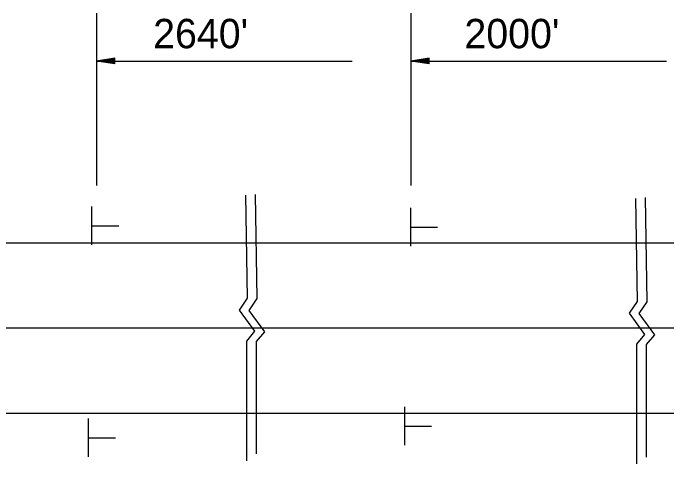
# Model space of a CAD drawing. Extents: x 1374027 to 1374537, y 380415 to 381405.
# Drawn here: x 1374072.71 to 1374086.06, y 380929.4 to 380938.61 of the extents above; entities that cross this region are included whole.
import ezdxf

# ---------------------------------------------------------------- set-up
doc = ezdxf.new("R2010")
doc.units = 0
doc.layers.add('Default', color=7, linetype='Continuous')

msp = doc.modelspace()

# ---------------------------------------------------------------- linework, layer by layer
at = {"layer": 'Default'}
for p, q in [((1374074.415, 380938.607), (1374074.415, 380935.086)), ((1374080.831, 380938.607), (1374080.831, 380935.086)), ((1374074.79, 380937.684), (1374074.415, 380937.627)), ((1374074.79, 380937.674), (1374074.478, 380937.627)), ((1374074.79, 380937.665), (1374074.542, 380937.627)), ((1374074.79, 380937.571), (1374074.79, 380937.684)), ((1374081.206, 380937.684), (1374080.831, 380937.627)), ((1374081.206, 380937.674), (1374080.894, 380937.627)), ((1374081.206, 380937.665), (1374080.958, 380937.627)), ((1374081.206, 380937.571), (1374081.206, 380937.684)), ((1374074.415, 380937.627), (1374079.634, 380937.627)), ((1374074.79, 380937.571), (1374074.415, 380937.627)), ((1374074.79, 380937.581), (1374074.478, 380937.627)), ((1374074.79, 380937.59), (1374074.542, 380937.627)), ((1374074.79, 380937.655), (1374074.605, 380937.627)), ((1374074.79, 380937.6), (1374074.605, 380937.627)), ((1374074.79, 380937.646), (1374074.668, 380937.627)), ((1374074.79, 380937.609), (1374074.668, 380937.627)), ((1374074.79, 380937.636), (1374074.731, 380937.627)), ((1374074.79, 380937.619), (1374074.731, 380937.627)), ((1374080.831, 380937.627), (1374086.05, 380937.627)), ((1374081.206, 380937.571), (1374080.831, 380937.627)), ((1374081.206, 380937.581), (1374080.894, 380937.627)), ((1374081.206, 380937.59), (1374080.958, 380937.627)), ((1374081.206, 380937.655), (1374081.021, 380937.627)), ((1374081.206, 380937.6), (1374081.021, 380937.627)), ((1374081.206, 380937.646), (1374081.084, 380937.627)), ((1374081.206, 380937.609), (1374081.084, 380937.627)), ((1374081.206, 380937.636), (1374081.147, 380937.627)), ((1374081.206, 380937.619), (1374081.147, 380937.627)), ((1374074.324, 380933.872), (1374074.324, 380934.654)), ((1374080.831, 380933.848), (1374080.831, 380934.631)), ((1374074.336, 380934.261), (1374074.87, 380934.261)), ((1374080.843, 380934.238), (1374081.377, 380934.238)), ((1374039.716, 380933.916), (1374181.443, 380933.916)), ((1374039.716, 380932.177), (1374181.443, 380932.177)), ((1374080.705, 380929.784), (1374080.705, 380930.566)), ((1374039.716, 380930.439), (1374181.443, 380930.439)), ((1374074.257, 380929.546), (1374074.257, 380930.328)), ((1374080.716, 380930.173), (1374081.25, 380930.173)), ((1374074.268, 380929.935), (1374074.802, 380929.935))]:
    msp.add_line(p, q, dxfattribs=at)
for points in [[(1374077.457, 380934.886), (1374077.489, 380932.783), (1374077.326, 380932.541), (1374077.643, 380932.109), (1374077.476, 380931.909), (1374077.476, 380929.463)], [(1374077.656, 380934.905), (1374077.689, 380932.775), (1374077.526, 380932.533), (1374077.843, 380932.1), (1374077.676, 380931.9), (1374077.676, 380929.604)], [(1374085.413, 380934.823), (1374085.445, 380932.72), (1374085.283, 380932.478), (1374085.599, 380932.045), (1374085.433, 380931.846), (1374085.432, 380929.4)], [(1374085.613, 380934.842), (1374085.645, 380932.711), (1374085.483, 380932.47), (1374085.799, 380932.037), (1374085.633, 380931.837), (1374085.632, 380929.54)]]:
    msp.add_lwpolyline(points, dxfattribs=at)

# ---------------------------------------------------------------- texts
for s, p in [("2640'", (1374075.573, 380937.888)), ("2000'", (1374081.924, 380937.888))]:
    msp.add_text(s, height=0.6, dxfattribs=at).set_placement(p)

doc.saveas('drawing.dxf')
